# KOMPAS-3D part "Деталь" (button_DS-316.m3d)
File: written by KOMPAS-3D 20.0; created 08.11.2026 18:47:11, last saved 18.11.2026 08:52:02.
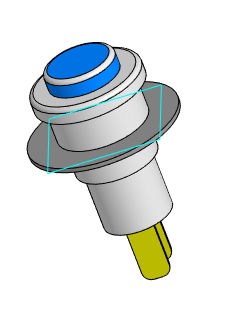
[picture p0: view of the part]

Document properties: Полное имя файла: D:\RicWork\Project-EPS32\box_compas\переключатели и кнопки\button_DS-316.m3d

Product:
- Part/product: Деталь
    Масса: 0.0102126

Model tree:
1. Эскиз:1
2. Элемент выдавливания:1
     Расстояние 1 = 1.8
3. Эскиз:2  (with: Элемент выдавливания:1)
4. Элемент выдавливания:2
     Расстояние 1 = 2
5. Скругление:1  (with: Элемент выдавливания:2)
     Радиус = 0.5
6. Скругление:2  (with: Элемент выдавливания:1)
     Радиус = 0.5
7. Эскиз:3  (with: Элемент выдавливания:1)
8. Элемент выдавливания:3
     Расстояние 1 = 5.8
9. Эскиз:4  (with: Элемент выдавливания:3)
10. Элемент выдавливания:4
     Расстояние 1 = 2.5
11. Эскиз:5  (with: Элемент выдавливания:4)
12. Элемент выдавливания:5
     Расстояние 1 = 6.7
13. Эскиз:6  (with: Элемент выдавливания:5)
14. Элемент выдавливания:6
     Расстояние 1 = 6.5
15. Скругление:3  (with: Элемент выдавливания:6)
     Радиус = 1
16. Эскиз:8  (with: Элемент выдавливания:4, Элемент выдавливания:5, Элемент выдавливания:6, Скругление:3, Элемент выдавливания:3, Элемент выдавливания:1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)
17. Смещенная плоскость:1  (with: Элемент выдавливания:1)
     Расстояние = 4.5
18. Эскиз:9  (with: Элемент выдавливания:3)
19. Элемент выдавливания:7
     Расстояние 2 = 0.5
